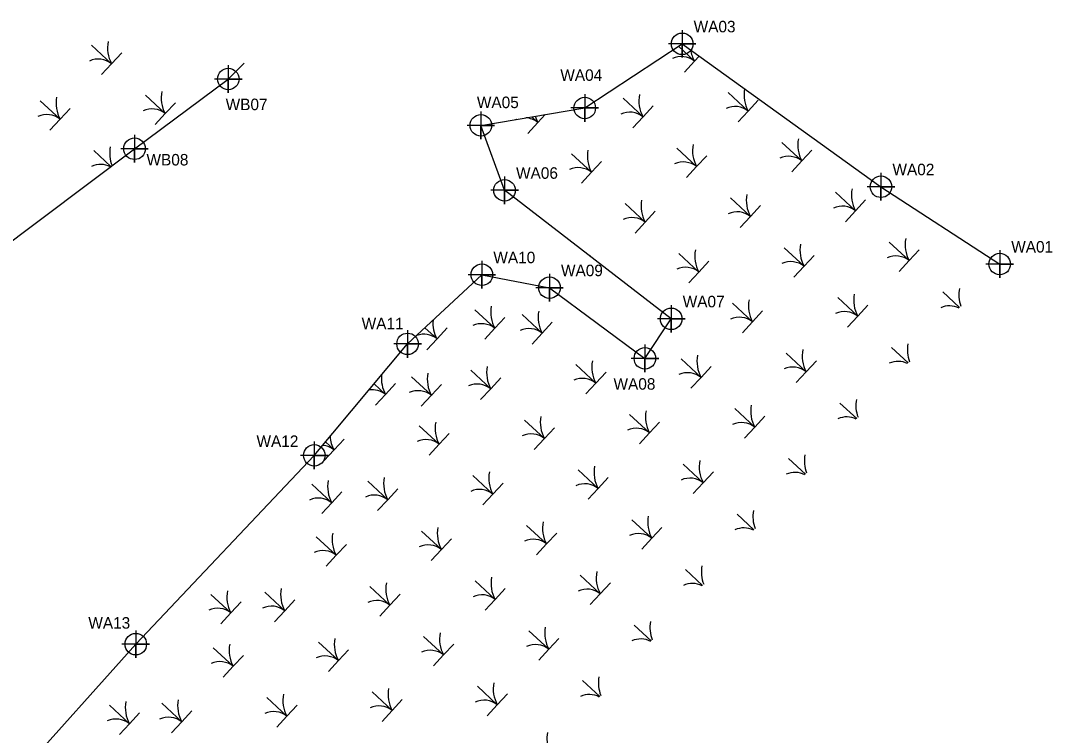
# Model space of a CAD drawing. Extents: x 2130226 to 2130625, y 149525 to 150037.
# Drawn here: x 2130401.2 to 2130625.4, y 149721.4 to 149876.7 of the extents above; entities that cross this region are included whole.
import ezdxf

# ---------------------------------------------------------------- set-up
doc = ezdxf.new("R2010")
doc.units = 0
for name, color, linetype in [('Exist Environmental Wetland Boundary', 7, 'Continuous'), ('Exist Environmental Wetland Boundary Cogo Number', 7, 'Continuous'), ('Exist Environmental Wetland Boundary Cogo Point CELL', 7, 'Continuous')]:
    doc.layers.add(name, color=color, linetype=linetype)

msp = doc.modelspace()

# ---------------------------------------------------------------- linework, layer by layer
at = {"layer": 'Exist Environmental Wetland Boundary'}
for points in [[(2130267.29, 149579.38), (2130312.46, 149626), (2130340.44, 149647.02), (2130369.49, 149683.11), (2130400.77, 149712.88), (2130426.19, 149741.24), (2130464.98, 149782.24), (2130485.26, 149806.46), (2130501.4, 149821.48), (2130516.1, 149818.66), (2130536.83, 149803.31), (2130542.55, 149811.9), (2130506.33, 149839.82), (2130501.18, 149853.93), (2130523.76, 149857.7), (2130544.93, 149871.63), (2130588.13, 149840.59), (2130613.94, 149823.8)], [(2130236.94, 149758.63), (2130284.36, 149741.14), (2130302.13, 149729.77), (2130335.9, 149765.49), (2130385.31, 149818.32), (2130425.92, 149848.84), (2130446.29, 149863.99), (2130449.73, 149867.45)]]:
    msp.add_lwpolyline(points, dxfattribs=at)
at = {"layer": 'Exist Environmental Wetland Boundary Cogo Point CELL'}
for p, q in [((2130504.51, 149844.81), (2130504.56, 149844.86)), ((2130527.89, 149823.2), (2130527.9, 149823.21))]:
    msp.add_line(p, q, dxfattribs=at)
for points in [[(2130544.93, 149874.63), (2130544.93, 149868.63), (2130544.93, 149871.63), (2130547.93, 149871.63), (2130541.93, 149871.63)], [(2130418.74, 149864.95), (2130420.94, 149867.31), (2130416.6, 149871.34), (2130420.94, 149867.31), (2130423.13, 149869.68)], [(2130545.41, 149865.48), (2130547.61, 149867.85), (2130544.11, 149871.09)], [(2130544.11, 149871.09), (2130547.61, 149867.85), (2130548.64, 149868.96)], [(2130446.29, 149866.99), (2130446.29, 149860.99), (2130446.29, 149863.99), (2130449.29, 149863.99), (2130443.29, 149863.99)], [(2130557.08, 149854.66), (2130559.27, 149857.02), (2130554.94, 149861.05), (2130559.27, 149857.02), (2130561.47, 149859.38)], [(2130407.55, 149852.89), (2130409.75, 149855.25), (2130405.41, 149859.28), (2130409.75, 149855.25), (2130411.94, 149857.62)], [(2130430.41, 149854.12), (2130432.6, 149856.49), (2130428.27, 149860.51), (2130432.6, 149856.49), (2130434.8, 149858.85)], [(2130523.76, 149860.7), (2130523.76, 149854.7), (2130523.76, 149857.7), (2130526.76, 149857.7), (2130520.76, 149857.7)], [(2130534.22, 149853.42), (2130536.42, 149855.79), (2130532.08, 149859.81), (2130536.42, 149855.79), (2130538.61, 149858.15)], [(2130501.18, 149856.93), (2130501.18, 149850.93), (2130501.18, 149853.93), (2130504.18, 149853.93), (2130498.18, 149853.93)], [(2130512.24, 149855.78), (2130513.56, 149854.56), (2130515.14, 149856.26)], [(2130511.36, 149852.19), (2130513.56, 149854.56), (2130512.24, 149855.78)], [(2130425.92, 149851.84), (2130425.92, 149845.84), (2130425.92, 149848.84), (2130428.92, 149848.84), (2130422.92, 149848.84)], [(2130568.75, 149843.83), (2130570.94, 149846.19), (2130566.6, 149850.22), (2130570.94, 149846.19), (2130573.14, 149848.56)], [(2130420.8, 149845), (2130417.08, 149848.45), (2130420.8, 149845)], [(2130523.03, 149841.36), (2130525.23, 149843.73), (2130520.89, 149847.75), (2130525.23, 149843.73), (2130527.42, 149846.09)], [(2130545.89, 149842.6), (2130548.08, 149844.96), (2130543.75, 149848.99), (2130548.08, 149844.96), (2130550.28, 149847.33)], [(2130506.33, 149842.82), (2130506.33, 149836.82), (2130506.33, 149839.82), (2130509.33, 149839.82), (2130503.33, 149839.82)], [(2130588.13, 149843.59), (2130588.13, 149837.59), (2130588.13, 149840.59), (2130591.13, 149840.59), (2130585.13, 149840.59)], [(2130580.42, 149833), (2130582.61, 149835.37), (2130578.27, 149839.39), (2130582.61, 149835.37), (2130584.8, 149837.73)], [(2130534.7, 149830.54), (2130536.89, 149832.9), (2130532.56, 149836.93), (2130536.89, 149832.9), (2130539.09, 149835.27)], [(2130557.56, 149831.77), (2130559.75, 149834.13), (2130555.41, 149838.16), (2130559.75, 149834.13), (2130561.95, 149836.5)], [(2130569.23, 149820.94), (2130571.42, 149823.31), (2130567.08, 149827.33), (2130571.42, 149823.31), (2130573.61, 149825.67)], [(2130592.08, 149822.17), (2130594.28, 149824.54), (2130589.94, 149828.56), (2130594.28, 149824.54), (2130596.47, 149826.9)], [(2130546.37, 149819.71), (2130548.56, 149822.07), (2130544.22, 149826.1), (2130548.56, 149822.07), (2130550.76, 149824.44)], [(2130613.94, 149826.8), (2130613.94, 149820.8), (2130613.94, 149823.8), (2130616.94, 149823.8), (2130610.94, 149823.8)], [(2130501.4, 149824.48), (2130501.4, 149818.48), (2130501.4, 149821.48), (2130504.4, 149821.48), (2130498.4, 149821.48)], [(2130516.1, 149821.66), (2130516.1, 149815.66), (2130516.1, 149818.66), (2130519.1, 149818.66), (2130513.1, 149818.66)], [(2130580.89, 149810.12), (2130583.09, 149812.48), (2130578.75, 149816.5), (2130583.09, 149812.48), (2130585.28, 149814.84)], [(2130605.22, 149814.38), (2130601.61, 149817.74), (2130605.22, 149814.38)], [(2130502.02, 149807.47), (2130504.21, 149809.84), (2130499.87, 149813.86), (2130504.21, 149809.84), (2130506.41, 149812.2)], [(2130542.55, 149814.9), (2130542.55, 149808.9), (2130542.55, 149811.9), (2130545.55, 149811.9), (2130539.55, 149811.9)], [(2130558.04, 149808.88), (2130560.23, 149811.25), (2130555.89, 149815.27), (2130560.23, 149811.25), (2130562.42, 149813.61)], [(2130512.32, 149806.42), (2130514.51, 149808.78), (2130510.18, 149812.81), (2130514.51, 149808.78), (2130516.71, 149811.15)], [(2130485.26, 149809.46), (2130485.26, 149803.46), (2130485.26, 149806.46), (2130488.26, 149806.46), (2130482.26, 149806.46)], [(2130489.46, 149805.19), (2130491.66, 149807.55), (2130489.04, 149809.98)], [(2130489.04, 149809.98), (2130491.66, 149807.55), (2130493.85, 149809.92)], [(2130536.83, 149806.31), (2130536.83, 149800.31), (2130536.83, 149803.31), (2130539.83, 149803.31), (2130533.83, 149803.31)], [(2130594.05, 149802.31), (2130590.42, 149805.68), (2130594.05, 149802.31)], [(2130546.85, 149796.82), (2130549.04, 149799.19), (2130544.7, 149803.21), (2130549.04, 149799.19), (2130551.23, 149801.55)], [(2130569.7, 149798.06), (2130571.9, 149800.42), (2130567.56, 149804.45), (2130571.9, 149800.42), (2130574.09, 149802.78)], [(2130501.13, 149794.36), (2130503.32, 149796.72), (2130498.99, 149800.75), (2130503.32, 149796.72), (2130505.52, 149799.09)], [(2130523.99, 149795.59), (2130526.18, 149797.96), (2130521.84, 149801.98), (2130526.18, 149797.96), (2130528.38, 149800.32)], [(2130488.23, 149792.92), (2130490.43, 149795.29), (2130486.09, 149799.31), (2130490.43, 149795.29), (2130492.62, 149797.65)], [(2130478, 149797.78), (2130480.47, 149795.49), (2130482.66, 149797.86)], [(2130478.27, 149793.13), (2130480.47, 149795.49), (2130478, 149797.78)], [(2130582.88, 149790.23), (2130579.23, 149793.62), (2130582.88, 149790.23)], [(2130558.51, 149786), (2130560.71, 149788.36), (2130556.37, 149792.39), (2130560.71, 149788.36), (2130562.9, 149790.73)], [(2130512.8, 149783.53), (2130514.99, 149785.9), (2130510.65, 149789.92), (2130514.99, 149785.9), (2130517.19, 149788.26)], [(2130535.66, 149784.76), (2130537.85, 149787.13), (2130533.51, 149791.15), (2130537.85, 149787.13), (2130540.04, 149789.49)], [(2130489.94, 149782.3), (2130492.13, 149784.66), (2130487.8, 149788.69), (2130492.13, 149784.66), (2130494.33, 149787.03)], [(2130464.98, 149785.24), (2130464.98, 149779.24), (2130464.98, 149782.24), (2130467.98, 149782.24), (2130461.98, 149782.24)], [(2130467.08, 149781.07), (2130469.28, 149783.43), (2130467.42, 149785.15)], [(2130467.42, 149785.15), (2130469.28, 149783.43), (2130471.47, 149785.8)], [(2130547.32, 149773.94), (2130549.52, 149776.3), (2130545.18, 149780.33), (2130549.52, 149776.3), (2130551.71, 149778.67)], [(2130571.71, 149778.16), (2130568.04, 149781.56), (2130571.71, 149778.16)], [(2130501.61, 149771.47), (2130503.8, 149773.84), (2130499.46, 149777.86), (2130503.8, 149773.84), (2130506, 149776.2)], [(2130524.47, 149772.7), (2130526.66, 149775.07), (2130522.32, 149779.09), (2130526.66, 149775.07), (2130528.85, 149777.43)], [(2130466.59, 149769.6), (2130468.78, 149771.96), (2130464.44, 149775.98), (2130468.78, 149771.96), (2130470.98, 149774.32)], [(2130478.75, 149770.24), (2130480.94, 149772.61), (2130476.61, 149776.63), (2130480.94, 149772.61), (2130483.14, 149774.97)], [(2130560.53, 149766.08), (2130556.85, 149769.5), (2130560.53, 149766.08)], [(2130513.28, 149760.65), (2130515.47, 149763.01), (2130511.13, 149767.04), (2130515.47, 149763.01), (2130517.66, 149765.37)], [(2130536.13, 149761.88), (2130538.33, 149764.24), (2130533.99, 149768.27), (2130538.33, 149764.24), (2130540.52, 149766.61)], [(2130467.56, 149758.18), (2130469.75, 149760.55), (2130465.42, 149764.57), (2130469.75, 149760.55), (2130471.95, 149762.91)], [(2130490.42, 149759.41), (2130492.61, 149761.78), (2130488.27, 149765.8), (2130492.61, 149761.78), (2130494.81, 149764.14)], [(2130524.94, 149749.82), (2130527.14, 149752.18), (2130522.8, 149756.21), (2130527.14, 149752.18), (2130529.33, 149754.55)], [(2130549.36, 149754), (2130545.66, 149757.44), (2130549.36, 149754)], [(2130479.23, 149747.35), (2130481.42, 149749.72), (2130477.08, 149753.74), (2130481.42, 149749.72), (2130483.62, 149752.08)], [(2130502.09, 149748.59), (2130504.28, 149750.95), (2130499.94, 149754.98), (2130504.28, 149750.95), (2130506.47, 149753.32)], [(2130444.67, 149745.67), (2130446.87, 149748.04), (2130442.53, 149752.06), (2130446.87, 149748.04), (2130449.06, 149750.4)], [(2130456.37, 149746.12), (2130458.56, 149748.49), (2130454.23, 149752.51), (2130458.56, 149748.49), (2130460.76, 149750.85)], [(2130426.19, 149744.24), (2130426.19, 149738.24), (2130426.19, 149741.24), (2130429.19, 149741.24), (2130423.19, 149741.24)], [(2130513.75, 149737.76), (2130515.95, 149740.12), (2130511.61, 149744.15), (2130515.95, 149740.12), (2130518.14, 149742.49)], [(2130538.19, 149741.93), (2130534.47, 149745.38), (2130538.19, 149741.93)], [(2130490.9, 149736.53), (2130493.09, 149738.89), (2130488.75, 149742.92), (2130493.09, 149738.89), (2130495.28, 149741.26)], [(2130445.18, 149734.06), (2130447.37, 149736.43), (2130443.04, 149740.45), (2130447.37, 149736.43), (2130449.57, 149738.79)], [(2130468.04, 149735.29), (2130470.23, 149737.66), (2130465.89, 149741.68), (2130470.23, 149737.66), (2130472.43, 149740.02)], [(2130527.02, 149729.85), (2130523.28, 149733.32), (2130527.02, 149729.85)], [(2130479.71, 149724.47), (2130481.9, 149726.83), (2130477.56, 149730.86), (2130481.9, 149726.83), (2130484.09, 149729.2)], [(2130502.56, 149725.7), (2130504.76, 149728.06), (2130500.42, 149732.09), (2130504.76, 149728.06), (2130506.95, 149730.43)], [(2130456.85, 149723.24), (2130459.04, 149725.6), (2130454.7, 149729.63), (2130459.04, 149725.6), (2130461.24, 149727.96)], [(2130422.62, 149721.6), (2130424.81, 149723.97), (2130420.48, 149727.99), (2130424.81, 149723.97), (2130427.01, 149726.33)], [(2130433.99, 149722), (2130436.18, 149724.37), (2130431.85, 149728.39), (2130436.18, 149724.37), (2130438.38, 149726.73)]]:
    msp.add_lwpolyline(points, dxfattribs=at)
for centre in [(2130544.93, 149871.63), (2130446.29, 149863.99), (2130523.76, 149857.7), (2130501.18, 149853.93), (2130425.92, 149848.84), (2130588.13, 149840.59), (2130506.33, 149839.82), (2130613.94, 149823.8), (2130501.4, 149821.48), (2130516.1, 149818.66), (2130542.55, 149811.9), (2130485.26, 149806.46), (2130536.83, 149803.31), (2130464.98, 149782.24), (2130426.19, 149741.24)]:
    msp.add_circle(centre, 2.34, dxfattribs=at)
for centre, radius, start, end in [((2130427.26, 149870.78), 7.21, 169.2688, 208.7635), ((2130553.92, 149871.32), 7.21, 188.1433, 208.7635), ((2130418.05, 149863.71), 4.61, 51.2816, 114.6763), ((2130544.72, 149864.25), 4.61, 51.2816, 114.6763), ((2130438.92, 149859.95), 7.21, 169.2688, 208.7635), ((2130565.59, 149860.49), 7.21, 169.2688, 208.7635), ((2130416.07, 149858.72), 7.21, 169.2688, 208.7635), ((2130542.73, 149859.26), 7.21, 169.2688, 208.7635), ((2130406.86, 149851.66), 4.61, 51.2816, 114.6763), ((2130429.72, 149852.89), 4.61, 51.2816, 114.6763), ((2130533.53, 149852.19), 4.61, 51.2816, 114.6763), ((2130556.39, 149853.42), 4.61, 51.2816, 114.6763), ((2130510.67, 149850.96), 4.61, 112.3231, 114.6763), ((2130510.67, 149850.96), 4.61, 51.2816, 86.6205), ((2130519.88, 149858.02), 7.21, 197.1227, 208.7635), ((2130554.4, 149848.43), 7.21, 169.2688, 208.7635), ((2130577.26, 149849.66), 7.21, 169.2688, 208.7635), ((2130427.73, 149847.9), 7.21, 169.2688, 202.0821), ((2130531.54, 149847.2), 7.21, 169.2688, 208.7635), ((2130418.53, 149840.83), 4.61, 62.1685, 114.6763), ((2130545.2, 149841.36), 4.61, 51.2816, 114.6763), ((2130568.06, 149842.59), 4.61, 51.2816, 114.6763), ((2130522.34, 149840.13), 4.61, 51.2816, 114.6763), ((2130566.07, 149837.6), 7.21, 169.2688, 208.7635), ((2130588.93, 149838.83), 7.21, 169.2688, 208.7635), ((2130543.21, 149836.37), 7.21, 169.2688, 208.7635), ((2130579.73, 149831.77), 4.61, 51.2816, 114.6763), ((2130534.01, 149829.3), 4.61, 51.2816, 114.6763), ((2130556.87, 149830.54), 4.61, 51.2816, 114.6763), ((2130600.6, 149828.01), 7.21, 169.2688, 208.7635), ((2130577.74, 149826.78), 7.21, 169.2688, 208.7635), ((2130532.02, 149824.31), 7.21, 169.2688, 170.5244), ((2130554.88, 149825.54), 7.21, 169.2688, 208.7635), ((2130591.39, 149820.94), 4.61, 51.2816, 114.6763), ((2130545.68, 149818.48), 4.61, 51.2816, 114.6763), ((2130568.54, 149819.71), 4.61, 51.2816, 114.6763), ((2130612.27, 149817.18), 7.21, 169.2688, 200.2547), ((2130566.55, 149814.72), 7.21, 169.2688, 208.7635), ((2130589.41, 149815.95), 7.21, 169.2688, 208.7635), ((2130510.53, 149813.31), 7.21, 169.2688, 208.7635), ((2130603.06, 149810.11), 4.61, 63.7633, 114.6763), ((2130497.97, 149811.02), 7.21, 175.3569, 208.7635), ((2130520.83, 149812.25), 7.21, 169.2688, 208.7635), ((2130557.35, 149807.65), 4.61, 51.2816, 114.6763), ((2130580.2, 149808.88), 4.61, 51.2816, 114.6763), ((2130501.33, 149806.24), 4.61, 51.2816, 114.6763), ((2130511.63, 149805.18), 4.61, 51.2816, 114.6763), ((2130488.77, 149803.95), 4.61, 51.2816, 109.2849), ((2130578.22, 149803.89), 7.21, 169.2688, 208.7635), ((2130601.08, 149805.12), 7.21, 169.2688, 200.4706), ((2130532.5, 149801.42), 7.21, 169.2688, 208.7635), ((2130555.36, 149802.66), 7.21, 169.2688, 208.7635), ((2130591.87, 149798.05), 4.61, 63.4496, 114.6763), ((2130509.64, 149800.19), 7.21, 169.2688, 208.7635), ((2130546.16, 149795.59), 4.61, 51.2816, 114.6763), ((2130569.01, 149796.82), 4.61, 51.2816, 114.6763), ((2130486.78, 149798.96), 7.21, 173.9931, 208.7635), ((2130496.75, 149798.75), 7.21, 169.2688, 208.7635), ((2130523.3, 149794.36), 4.61, 51.2816, 114.6763), ((2130477.58, 149791.89), 4.61, 51.2816, 98.6943), ((2130487.54, 149791.69), 4.61, 51.2816, 114.6763), ((2130500.44, 149793.13), 4.61, 51.2816, 114.6763), ((2130589.89, 149793.06), 7.21, 169.2688, 200.6861), ((2130544.17, 149790.6), 7.21, 169.2688, 208.7635), ((2130567.03, 149791.83), 7.21, 169.2688, 208.7635), ((2130498.45, 149788.13), 7.21, 169.2688, 208.7635), ((2130521.31, 149789.37), 7.21, 169.2688, 208.7635), ((2130557.82, 149784.76), 4.61, 51.2816, 114.6763), ((2130580.68, 149785.99), 4.61, 63.1363, 114.6763), ((2130512.11, 149782.3), 4.61, 51.2816, 114.6763), ((2130534.97, 149783.53), 4.61, 51.2816, 114.6763), ((2130475.59, 149786.9), 7.21, 184.5312, 208.7635), ((2130489.25, 149781.07), 4.61, 51.2816, 114.6763), ((2130466.39, 149779.83), 4.61, 51.2816, 84.7434), ((2130578.7, 149781), 7.21, 169.2688, 200.9012), ((2130555.84, 149779.77), 7.21, 169.2688, 208.7635), ((2130510.12, 149777.31), 7.21, 169.2688, 208.7635), ((2130532.98, 149778.54), 7.21, 169.2688, 208.7635), ((2130569.49, 149773.94), 4.61, 62.8235, 114.6763), ((2130475.1, 149775.43), 7.21, 169.2688, 208.7635), ((2130487.26, 149776.07), 7.21, 169.2688, 208.7635), ((2130523.78, 149771.47), 4.61, 51.2816, 114.6763), ((2130546.63, 149772.7), 4.61, 51.2816, 114.6763), ((2130478.06, 149769.01), 4.61, 51.2816, 114.6763), ((2130500.92, 149770.24), 4.61, 51.2816, 114.6763), ((2130465.9, 149768.36), 4.61, 51.2816, 114.6763), ((2130544.65, 149767.71), 7.21, 169.2688, 208.7635), ((2130567.51, 149768.94), 7.21, 169.2688, 201.1158), ((2130498.93, 149765.25), 7.21, 169.2688, 208.7635), ((2130521.79, 149766.48), 7.21, 169.2688, 208.7635), ((2130476.07, 149764.01), 7.21, 169.2688, 208.7635), ((2130535.44, 149760.64), 4.61, 51.2816, 114.6763), ((2130558.3, 149761.88), 4.61, 62.5113, 114.6763), ((2130489.73, 149758.18), 4.61, 51.2816, 114.6763), ((2130512.59, 149759.41), 4.61, 51.2816, 114.6763), ((2130466.87, 149756.95), 4.61, 51.2816, 114.6763), ((2130556.32, 149756.88), 7.21, 169.2688, 201.3301), ((2130510.6, 149754.42), 7.21, 169.2688, 208.7635), ((2130533.46, 149755.65), 7.21, 169.2688, 208.7635), ((2130464.88, 149751.96), 7.21, 169.2688, 208.7635), ((2130487.74, 149753.19), 7.21, 169.2688, 208.7635), ((2130524.25, 149748.58), 4.61, 51.2816, 114.6763), ((2130547.11, 149749.82), 4.61, 62.1994, 114.6763), ((2130453.19, 149751.51), 7.21, 169.2688, 208.7635), ((2130501.4, 149747.35), 4.61, 51.2816, 114.6763), ((2130443.98, 149744.44), 4.61, 51.2816, 114.6763), ((2130455.68, 149744.89), 4.61, 51.2816, 114.6763), ((2130478.54, 149746.12), 4.61, 51.2816, 114.6763), ((2130522.27, 149743.59), 7.21, 169.2688, 208.7635), ((2130545.13, 149744.82), 7.21, 169.2688, 201.544), ((2130476.55, 149741.13), 7.21, 169.2688, 208.7635), ((2130499.41, 149742.36), 7.21, 169.2688, 208.7635), ((2130535.92, 149737.76), 4.61, 61.8881, 114.6763), ((2130453.69, 149739.9), 7.21, 169.2688, 208.7635), ((2130490.21, 149735.29), 4.61, 51.2816, 114.6763), ((2130513.06, 149736.53), 4.61, 51.2816, 114.6763), ((2130444.49, 149732.83), 4.61, 51.2816, 114.6763), ((2130467.35, 149734.06), 4.61, 51.2816, 114.6763), ((2130533.94, 149732.77), 7.21, 169.2688, 201.7575), ((2130488.22, 149730.3), 7.21, 169.2688, 208.7635), ((2130511.08, 149731.53), 7.21, 169.2688, 208.7635), ((2130431.13, 149727.44), 7.21, 169.2688, 208.7635), ((2130442.5, 149727.84), 7.21, 169.2688, 208.7635), ((2130465.36, 149729.07), 7.21, 169.2688, 208.7635), ((2130501.87, 149724.47), 4.61, 51.2816, 114.6763), ((2130524.73, 149725.7), 4.61, 61.5771, 114.6763), ((2130456.16, 149722), 4.61, 51.2816, 114.6763), ((2130479.02, 149723.23), 4.61, 51.2816, 114.6763), ((2130421.93, 149720.37), 4.61, 51.2816, 114.6763), ((2130433.3, 149720.77), 4.61, 51.2816, 114.6763), ((2130522.75, 149720.71), 7.21, 169.2688, 201.9706)]:
    msp.add_arc(centre, radius, start, end, dxfattribs=at)

# ---------------------------------------------------------------- texts
at = {"layer": 'Exist Environmental Wetland Boundary Cogo Number'}
for s, p in [('WA03', (2130547.43, 149874.13)), ('WA04', (2130518.45, 149863.59)), ('WB07', (2130445.73, 149857.23)), ('WA05', (2130500.32, 149857.67)), ('WB08', (2130428.52, 149845.21)), ('WA02', (2130590.63, 149843.09)), ('WA06', (2130508.83, 149842.32)), ('WA01', (2130616.44, 149826.3)), ('WA10', (2130503.9, 149823.98)), ('WA09', (2130518.6, 149821.16)), ('WA07', (2130545.05, 149814.4)), ('WA11', (2130475.28, 149809.62)), ('WA08', (2130530.01, 149796.51)), ('WA12', (2130452.43, 149784.07)), ('WA13', (2130415.88, 149744.61))]:
    msp.add_text(s, height=2.5, dxfattribs=at).set_placement(p)

doc.saveas('drawing.dxf')
